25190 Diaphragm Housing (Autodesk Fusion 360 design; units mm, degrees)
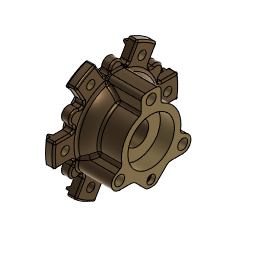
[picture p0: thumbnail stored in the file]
parameter "Bell_Tolerance" = 0.0992 (= "( 1 / 256 ) * 1 in")
parameter "Alignment_Boss_Tolerance" = 0.1984 (= "( 1 / 128 ) * 1 in")
parameter "Dowel_Hole_Tolerance" = 0.0992 (= "( 1 / 256 ) * 1 in")
parameter "Dowl_And_Bell_Depth_Tolerance" = 0.7937 (= "( 1 / 32 ) * 1 in")
sketch "Main Profile" plane through (0, 0, 0) normal (0, 1, 0) x axis (1, 0, 0)
  line L1 (0, 25.4) -> (0, -25.4)
  line L2 (0, -26.9875) -> (0, -25.4)
  line L3 (1.3048, -26.9875) -> (0, -26.9875)
  line L4 (3.7879, -13.6274) -> (1.5528, -24.1426)
  line L5 (31.75, -11.1125) -> (6.8935, -11.1125)
  line L6 (65.0875, 0) -> (0, 0)
  line L7 (6.2281, -21.4795) -> (4.0817, -25.3518)
  line L8 (4.3224, -11.1125) -> (6.8935, -11.1125)
  line L9 (3.7879, -13.6274) -> (4.3224, -11.1125)
  line L10 (19.05, -19.8438) -> (9.0051, -19.8438)
  line L11 (1.3048, -26.9875) -> (3.175, -26.9875)
  line L12 (7.1348, -19.8438) -> (9.0051, -19.8438)
  line L13 (6.2281, -21.4795) -> (7.1348, -19.8438)
  line L14 (3.175, -26.9875) -> (4.0817, -25.3518)
  line L15 (31.75, -22.225) -> (31.75, -11.1125)
  line L16 (44.45, -22.225) -> (31.75, -22.225)
  line L17 (65.0875, 0) -> (65.0875, -34.925)
  line L18 (44.45, -44.45) -> (44.45, -22.225)
  line L19 (3.175, -44.45) -> (44.45, -44.45)
  line L20 (3.175, -41.275) -> (3.175, -44.45)
  line L21 (0, -41.275) -> (3.175, -41.275)
  line L22 (0, -38.1) -> (0, -41.275)
  line L23 (0, -38.1) -> (0, -26.9875)
  line L24 (22.225, -11.1125) -> (22.225, -44.45)
  line L25 (96.52, -34.925) -> (22.225, -34.925)
  line L26 (20.6375, -39.6875) -> (44.45, -39.6875)
  line L27 (20.6375, -30.1625) -> (20.6375, -39.6875)
  line L28 (44.45, -30.1625) -> (20.6375, -30.1625)
  line L29 (25.4, -30.1625) -> (20.6375, -34.925)
  line L30 (25.4, -39.6875) -> (20.6375, -34.925)
  line L31 (44.45, -42.8625) -> (3.175, -42.8625)
  arc A1 centre (0, -23.8125) radius 1.5875 clockwise from (1.5528, -24.1426) to (0, -25.4)
  arc A2 centre (1.3048, -23.8125) radius 3.175 clockwise from (4.0817, -25.3518) to (1.3048, -26.9875)
  arc A3 centre (6.8935, -14.2875) radius 3.175 clockwise from (3.7879, -13.6274) to (6.8935, -11.1125)
  arc A4 centre (9.0051, -23.0187) radius 3.175 clockwise from (6.2281, -21.4795) to (9.0051, -19.8438)
  arc A5 centre (19.05, -23.0187) radius 3.175 clockwise from (19.05, -19.8438) to (21.8627, -24.4917)
  arc A6 centre (-0.6386, -12.708) radius 25.4 clockwise from (21.8627, -24.4917) to (0, -38.1)
  point P4 (0, 0)
  point P1 (0, 0)
  point P6 (0, -23.8125)
  point P15 (0, 0)
  point P24 (6.2281, -21.4795)
  point P22 (3.175, -26.9875)
  point P25 (3.175, -26.9875)
  point P16 (65.0875, 0)
  point P29 (65.0875, 0)
  point P39 (22.225, -11.1125)
  point P38 (22.225, -44.45)
  point P40 (22.225, -34.925)
  point P42 (44.45, -34.925)
  point P28 (65.0875, -34.925)
  point P43 (44.45, -39.6875)
  point P46 (44.45, -30.1625)
  point P47 (20.6375, -34.925)
  point P48 (25.4, -30.1625)
  point P49 (25.4, -39.6875)
  point P50 (3.175, -42.8625)
  point P51 (44.45, -42.8625)
  point P2 (0, -25.4)
  point P3 (0, 25.4)
  point P7 (0, -26.9875)
  point P26 (31.75, -22.225)
  point P27 (44.45, -22.225)
  point P33 (0, -41.275)
  point P34 (0, -38.1)
  point P32 (3.175, -41.275)
  point P44 (20.6375, -39.6875)
  point P45 (20.6375, -30.1625)
  vertical L1
  midpoint L1 P4
  coincident P1 P4
  coincident L1 P6
  parallel L1 L2
  perpendicular L2 L3
  tangent L3 A2
  tangent A1 L4
  tangent L4 A3
  tangent A3 L5
  horizontal L5
  coincident P1 P15
  horizontal L6
  tangent A2 L7
  tangent A3 L8
  parallel L4 L9
  tangent L7 A4
  horizontal L10
  tangent A4 L10
  horizontal L11
  tangent A4 L12
  coincident A4 P24
  tangent A4 L13
  parallel L7 L13
  tangent A2 L14
  coincident P22 P25
  perpendicular L5 L15
  perpendicular L15 L16
  vertical L17
  coincident P16 P29
  perpendicular L16 L18
  perpendicular L18 L19
  perpendicular L19 L20
  perpendicular L20 L21
  perpendicular L21 L22
  vertical L23
  tangent L10 A5
  tangent A5 A6
  vertical L24
  tangent A5 L24
  coincident L5 P39
  coincident L19 P38
  coincident L24 P40
  perpendicular L24 L25
  coincident L18 P42
  coincident L25 P42
  coincident P28 L25
  coincident L18 P43
  perpendicular L18 L26
  perpendicular L25 L27
  coincident L18 P46
  perpendicular L18 L28
  symmetric L25 L26 L28
  midpoint L27 P47
  coincident L28 P48
  coincident L26 P49
  perpendicular L29 L30
  symmetric L25 L29 L30
  horizontal L31
  midpoint L20 P50
  coincident L18 P51
  dimension "d4" distance P2 P3 = 50.8
  dimension "d5" distance P2 P7 = 1.5875 (= "( 1 / 16 ) * 1 in")
  dimension "d6" radius A3 = 3.175 (= "( 1 / 8 ) * 1 in")
  dimension "d7" distance L5 L6 = 11.1125
  dimension "d8" radius A2 = 3.175 (= "( 1 / 8 ) * 1 in")
  dimension "d9" radius A1 = 1.5875 (= "( 1 / 16 ) * 1 in")
  dimension "d12" radius A4 = 3.175 (= "( 1 / 8 ) * 1 in")
  dimension "d13" distance L5 L10 = 8.7313 (= "( 11 / 32 ) * 1 in")
  dimension "d14" distance P7 P22 = 3.175 (= "( 1 / 8 ) * 1 in")
  dimension "d15" angle L4 L7 = 17
  dimension "d17" distance L1 L17 = 65.0875 (= "2 9/16")
  dimension "d18" distance L6 L16 = 22.225 (= "( 7 / 8 ) * 1 in")
  dimension "d19" distance P26 P27 = 12.7 (= "( 1 / 2 ) * 1 in")
  dimension "d21" distance L6 L19 = 44.45 (= "1 3/4")
  dimension "d22" distance P33 P34 = 3.175 (= "( 1 / 8 ) * 1 in")
  dimension "d23" distance P32 P33 = 3.175 (= "( 1 / 8 ) * 1 in")
  dimension "d25" radius A5 = 3.175 (= "( 1 / 8 ) * 1 in")
  dimension "d28" distance L6 L25 = 34.925
  dimension "d32" distance P44 P45 = 9.525 (= "( 3 / 8 ) * 1 in")
  dimension "d33" distance L18 L27 = 23.8125 (= "( 15 / 16 ) * 1 in")
  dimension "d63" distance P4 P34 = 38.1 (= "1 1/2")
  dimension "d64" distance L24 L27 = 1.5875 (= "( 1 / 16 ) * 1 in")
  dimension "d73" distance L6 L31 = 42.8625
  dimension "d127" radius A6 = 25.4
  dimension "d133" distance L18 L22 = 44.45
  dimension "d137" angle L1 L4 = 12
  dimension "d16" Text1-Height = 3.175
  dimension "d29" Text2-Height = 3.175
revolve "Revolve1" sketch "Main Profile" AlongAngle 360
sketch "Flange Profile" plane through (44.45, 0, 0) normal (1, 0, 0) x axis (0, 1, 0)
  line L1 (0, 34.925) -> (0, 0)
  line L2 (-30.2459, -17.4625) -> (0, 0)
  line L3 (30.2459, -17.4625) -> (0, 0)
  line L4 (0, 44.45) -> (0, 34.925)
  line L5 (3.175, 44.45) -> (-3.175, 44.45)
  line L6 (9.525, 29.0994) -> (9.525, 38.1)
  line L7 (34.2147, -10.5884) -> (29.7259, -7.9968)
  line L8 (30.2459, -25.4) -> (16.6688, -25.4)
  line L9 (0, -31.75) -> (0, 0)
  line L10 (0, -38.1) -> (0, -31.75)
  line L11 (3.9688, -38.1) -> (-3.9688, -38.1)
  line L12 (16.6688, -25.4) -> (3.9688, -38.1)
  line L13 (-9.525, 29.0994) -> (-9.525, 38.1)
  line L14 (-34.2147, -10.5884) -> (-29.7259, -7.9968)
  line L15 (-30.2459, -25.4) -> (-16.6688, -25.4)
  line L16 (-16.6688, -25.4) -> (-3.9688, -38.1)
  line L17 (9.525, 26.9408) -> (9.525, 29.0994)
  line L18 (-9.525, 26.9408) -> (-9.525, 29.0994)
  circle C1 centre (0, 0) radius 22.225
  circle C2 centre (0, 34.925) radius 4.7625
  circle C3 centre (-30.2459, -17.4625) radius 4.7625
  circle C4 centre (30.2459, -17.4625) radius 4.7625
  arc A1 centre (3.175, 38.1) radius 6.35 clockwise from (3.175, 44.45) to (9.525, 38.1)
  arc A2 centre (12.7, 29.0994) radius 3.175 clockwise from (11.43, 26.1894) to (9.525, 29.0994)
  arc A3 centre (0, 0) radius 28.575 clockwise from (11.43, 26.1894) to (28.1821, -4.7225)
  arc A4 centre (31.3134, -5.2472) radius 3.175 clockwise from (29.7259, -7.9968) to (28.1821, -4.7225)
  arc A5 centre (30.2459, -17.4625) radius 7.9375 clockwise from (34.2147, -10.5884) to (30.2459, -25.4)
  circle C5 centre (0, -31.75) radius 3.9688
  arc A6 centre (-3.175, 38.1) radius 6.35 clockwise from (-9.525, 38.1) to (-3.175, 44.45)
  arc A7 centre (-12.7, 29.0994) radius 3.175 clockwise from (-9.525, 29.0994) to (-11.43, 26.1894)
  arc A8 centre (0, 0) radius 28.575 clockwise from (-28.1821, -4.7225) to (-11.43, 26.1894)
  arc A9 centre (-31.3134, -5.2472) radius 3.175 clockwise from (-28.1821, -4.7225) to (-29.7259, -7.9968)
  arc A10 centre (-30.2459, -17.4625) radius 7.9375 clockwise from (-30.2459, -25.4) to (-34.2147, -10.5884)
  circle C6 centre (0, 0) radius 42.8625
  arc A11 centre (0, 0) radius 28.575 clockwise from (-11.43, 26.1894) to (11.43, 26.1894)
  arc A12 centre (5.1027, 38.1) radius 4.4223 clockwise from (5.6897, 42.4832) to (9.525, 38.1)
  arc A13 centre (-5.1027, 38.1) radius 4.4223 clockwise from (-9.525, 38.1) to (-5.6897, 42.4832)
  point P1 (0, 0)
  point P3 (0, 0)
  point P4 (0, 34.925)
  point P5 (0, 34.925)
  point P12 (0, 34.925)
  point P16 (0, 44.45)
  point P13 (0, 44.45)
  point P26 (34.2147, -10.5884)
  point P29 (34.2147, -10.5884)
  point P31 (0, -31.75)
  point P32 (0, -31.75)
  point P33 (0, -31.75)
  point P37 (0, -38.1)
  point P34 (0, -38.1)
  point P15 (3.175, 44.45)
  point P40 (-3.175, 44.45)
  point P17 (9.525, 38.1)
  point P39 (-9.525, 38.1)
  point P19 (9.525, 29.0994)
  point P41 (-9.525, 29.0994)
  point P20 (11.43, 26.1894)
  point P43 (-11.43, 26.1894)
  point P22 (28.1821, -4.7225)
  point P45 (-28.1821, -4.7225)
  point P24 (29.7259, -7.9968)
  point P47 (-29.7259, -7.9968)
  point P48 (-34.2147, -10.5884)
  point P27 (16.6688, -25.4)
  point P52 (-16.6688, -25.4)
  point P28 (30.2459, -25.4)
  point P50 (-30.2459, -25.4)
  point P51 (-34.2147, -10.5884)
  point P36 (3.9688, -38.1)
  point P53 (-3.9688, -38.1)
  point P55 (9.525, 26.9408)
  point P56 (-9.525, 29.0994)
  point P57 (-9.525, 26.9408)
  point P58 (5.6897, 42.4832)
  point P61 (-9.525, 38.1)
  point P62 (-5.6897, 42.4832)
  point P23 (0, 0)
  point P35 (-3.9688, -38.1)
  coincident P1 P3
  vertical L1
  coincident P4 P5
  coincident P5 P12
  parallel L1 L4
  horizontal L5
  midpoint L5 P16
  coincident P13 P16
  tangent L5 A1
  vertical L6
  tangent A1 L6
  tangent L6 A2
  tangent A2 A3
  concentric C1 A3
  tangent A3 A4
  tangent A4 L7
  horizontal L8
  tangent L8 A5
  coincident P26 P29
  tangent L7 A5
  concentric C4 A5
  vertical L9
  coincident P31 P32
  coincident P32 P33
  vertical L10
  horizontal L11
  midpoint L11 P37
  coincident P34 L11
  coincident P34 P37
  symmetric L1 P15 P40
  symmetric L1 P17 P39
  symmetric L1 A1 A6
  symmetric L1 P19 P41
  symmetric L1 P20 P43
  symmetric L1 A2 A7
  symmetric L1 P22 P45
  symmetric L1 A3 A8
  symmetric L1 P24 P47
  symmetric L1 A4 A9
  symmetric L1 P26 P48
  symmetric L1 P27 P52
  symmetric L1 P28 P50
  symmetric L1 P29 P51
  symmetric L1 A5 A10
  symmetric L1 P36 P53
  tangent A8 A11
  coincident A11 P55
  tangent A2 L17
  symmetric L1 P19 P56
  symmetric L1 P55 P57
  coincident C6 P58
  tangent L6 A12
  tangent C6 A12
  symmetric L4 P17 P61
  symmetric L4 P58 P62
  symmetric L4 A12 A13
  tangent A5 C6
  dimension "d35" diameter C2 = 9.525 (= "( 3 / 8 ) * 1 in")
  dimension "d36" distance P3 P4 = 34.925 (= "1 3/8")
  dimension "d39" distance P5 L5 = 9.525 (= "( 3 / 8 ) * 1 in")
  dimension "d40" radius A1 = 6.35 (= "( 1 / 4 ) * 1 in")
  dimension "d41" distance P5 L6 = 9.525 (= "( 3 / 8 ) * 1 in")
  dimension "d42" radius A2 = 3.175 (= "( 1 / 8 ) * 1 in")
  dimension "d43" radius A3 = 28.575
  dimension "d44" radius A4 = 3.175 (= "( 1 / 8 ) * 1 in")
  dimension "d46" angle L7 L8 = 30
  dimension "d47" diameter C5 = 7.9375 (= "( 5 / 16 ) * 1 in")
  dimension "d48" distance P32 L11 = 6.35 (= "( 1 / 4 ) * 1 in")
  dimension "d49" distance P23 P32 = 31.75 (= "1 1/4")
  dimension "d50" angle L8 L12 = 135
  dimension "d51" distance P35 P36 = 7.9375 (= "( 5 / 16 ) * 1 in")
  dimension "d38" C-Pattern1-Angle = 360
extrude "Extrude1" cut sketch "Flange Profile" profile of A1 L6 A2 A3 A4 L7 L8 A5 L11 L12 A6 L13 A7 A8 A9 L14 A10 L15 L16 C6 A12 A13 against normal blind 33.3375
work_plane "WorkPlane1" RotateAngle 45
sketch "Body Profile" plane through (12.125, 0, 0) normal (0, -0.7071, 0.7071) x axis (1, 0, 0)
  line L1 (-1.0125, 35.2263) -> (-1.0125, 16.5498)
  curve K1 (-1.0125, 16.5498) -> (5.082, 15.3648)
  line L2 (7.0707, 16.5884) -> (7.0707, 28.575)
  line L3 (-1.0125, 38.755) -> (-1.0125, 35.2263)
  line L4 (11.0013, 28.575) -> (7.0707, 28.575)
  arc A1 centre (-12.7636, 12.708) radius 25.4 clockwise from (-1.0125, 35.2263) to (7.0707, 28.575)
  arc A2 centre (-12.7636, 12.708) radius 28.575 clockwise from (-1.0125, 38.755) to (11.0013, 28.575)
  point P5 (7.0707, 28.575)
  point P8 (7.0707, 28.575)
  point P3 (-1.0125, 35.2263)
  point P7 (-1.0125, 35.2263)
  coincident P5 P8
  coincident P3 P7
  vertical L3
  perpendicular L2 L4
  concentric A1 A2
  dimension "d55" radius A1 = 25.4
  dimension "d56" distance A1 A2 = 3.175 (= "( 1 / 8 ) * 1 in")
revolve "Revolve2" sketch "Body Profile" AlongAngle 360
sketch "Cap Flange Profile" plane through (3.175, 0, 0) normal (-1, 0, 0) x axis (0, -1, 0)
  line L1 (0, 44.45) -> (0, 0)
  line L2 (0, 50.8) -> (0, 44.45)
  line L3 (-43.9941, 25.4) -> (-38.4948, 22.225)
  line L4 (-38.4948, 22.225) -> (0, 0)
  line L5 (-43.9941, -25.4) -> (-38.4948, -22.225)
  line L6 (-38.4948, -22.225) -> (0, 0)
  line L7 (0, -50.8) -> (0, -44.45)
  line L8 (0, -44.45) -> (0, 0)
  line L9 (43.9941, -25.4) -> (38.4948, -22.225)
  line L10 (38.4948, -22.225) -> (0, 0)
  line L11 (43.9941, 25.4) -> (38.4948, 22.225)
  line L12 (38.4948, 22.225) -> (0, 0)
  line L13 (60.325, 0) -> (0, 0)
  line L14 (60.325, -11.1125) -> (60.325, 11.1125)
  line L15 (41.3969, 11.1125) -> (60.325, 11.1125)
  line L16 (41.3969, -11.1125) -> (60.325, -11.1125)
  line L17 (11.0748, 41.407) -> (20.5388, 57.7992)
  line L18 (39.7862, 46.6867) -> (20.5388, 57.7992)
  line L19 (30.3222, 30.2945) -> (39.7862, 46.6867)
  line L20 (-30.3222, 30.2945) -> (-39.7862, 46.6867)
  line L21 (-20.5388, 57.7992) -> (-39.7862, 46.6867)
  line L22 (-11.0748, 41.407) -> (-20.5388, 57.7992)
  line L23 (-41.3969, -11.1125) -> (-60.325, -11.1125)
  line L24 (-60.325, 11.1125) -> (-60.325, -11.1125)
  line L25 (-41.3969, 11.1125) -> (-60.325, 11.1125)
  line L26 (-11.0748, -41.407) -> (-20.5388, -57.7992)
  line L27 (-39.7862, -46.6867) -> (-20.5388, -57.7992)
  line L28 (-30.3222, -30.2945) -> (-39.7862, -46.6867)
  line L29 (30.3222, -30.2945) -> (39.7862, -46.6867)
  line L30 (20.5388, -57.7992) -> (39.7862, -46.6867)
  line L31 (11.0748, -41.407) -> (20.5388, -57.7992)
  circle C1 centre (0, 0) radius 41.275
  circle C2 centre (0, 44.45) radius 1.5875
  arc A1 centre (0, 44.45) radius 6.35 clockwise from (-6.3376, 44.8469) to (6.3376, 44.8469)
  arc A2 centre (9.5064, 45.0453) radius 3.175 clockwise from (8.8508, 41.9387) to (6.3376, 44.8469)
  arc A3 centre (-9.5064, 45.0453) radius 3.175 clockwise from (-6.3376, 44.8469) to (-8.8508, 41.9387)
  circle C3 centre (0, 44.45) radius 3.5719
  arc A4 centre (-38.4948, 22.225) radius 6.35 clockwise from (-42.0073, 16.9349) to (-35.6697, 27.9119)
  arc A5 centre (-34.2572, 30.7554) radius 3.175 clockwise from (-31.8946, 28.6344) to (-35.6697, 27.9119)
  arc A6 centre (-43.7636, 14.2899) radius 3.175 clockwise from (-42.0073, 16.9349) to (-40.7454, 13.3044)
  circle C4 centre (-38.4948, 22.225) radius 3.5719
  circle C5 centre (-38.4948, 22.225) radius 1.5875
  arc A7 centre (-38.4948, -22.225) radius 6.35 clockwise from (-35.6697, -27.9119) to (-42.0073, -16.9349)
  arc A8 centre (-43.7636, -14.2899) radius 3.175 clockwise from (-40.7454, -13.3044) to (-42.0073, -16.9349)
  arc A9 centre (-34.2572, -30.7554) radius 3.175 clockwise from (-35.6697, -27.9119) to (-31.8946, -28.6344)
  circle C6 centre (-38.4948, -22.225) radius 3.5719
  circle C7 centre (-38.4948, -22.225) radius 1.5875
  arc A10 centre (0, -44.45) radius 6.35 clockwise from (6.3376, -44.8469) to (-6.3376, -44.8469)
  arc A11 centre (-9.5064, -45.0453) radius 3.175 clockwise from (-8.8508, -41.9387) to (-6.3376, -44.8469)
  arc A12 centre (9.5064, -45.0453) radius 3.175 clockwise from (6.3376, -44.8469) to (8.8508, -41.9387)
  circle C8 centre (0, -44.45) radius 3.5719
  circle C9 centre (0, -44.45) radius 1.5875
  arc A13 centre (38.4948, -22.225) radius 6.35 clockwise from (42.0073, -16.9349) to (35.6697, -27.9119)
  arc A14 centre (34.2572, -30.7554) radius 3.175 clockwise from (31.8946, -28.6344) to (35.6697, -27.9119)
  arc A15 centre (43.7636, -14.2899) radius 3.175 clockwise from (42.0073, -16.9349) to (40.7454, -13.3044)
  circle C10 centre (38.4948, -22.225) radius 3.5719
  circle C11 centre (38.4948, -22.225) radius 1.5875
  arc A16 centre (38.4948, 22.225) radius 6.35 clockwise from (35.6697, 27.9119) to (42.0073, 16.9349)
  arc A17 centre (43.7636, 14.2899) radius 3.175 clockwise from (40.7454, 13.3044) to (42.0073, 16.9349)
  arc A18 centre (34.2572, 30.7554) radius 3.175 clockwise from (35.6697, 27.9119) to (31.8946, 28.6344)
  circle C12 centre (38.4948, 22.225) radius 3.5719
  circle C13 centre (38.4948, 22.225) radius 1.5875
  circle C14 centre (0, 0) radius 60.325
  circle C15 centre (0, 0) radius 42.8625
  circle C16 centre (49.2125, 0) radius 3.9688
  circle C17 centre (24.6063, 42.6193) radius 3.9688
  circle C18 centre (-24.6062, 42.6193) radius 3.9688
  circle C19 centre (-49.2125, 0) radius 3.9688
  circle C20 centre (-24.6063, -42.6193) radius 3.9688
  circle C21 centre (24.6062, -42.6193) radius 3.9688
  arc A19 centre (9.5071, 45.0487) radius 3.1785 clockwise from (12.2597, 43.4595) to (8.8508, 41.9387)
  arc A20 centre (-9.5071, 45.0487) radius 3.1785 clockwise from (-8.8508, 41.9387) to (-12.2597, 43.4595)
  arc A21 centre (-43.7669, 14.291) radius 3.1785 clockwise from (-40.7454, 13.3044) to (-43.7669, 11.1125)
  arc A22 centre (-34.2598, 30.7577) radius 3.1785 clockwise from (-31.5071, 32.347) to (-31.8946, 28.6344)
  arc A23 centre (-34.2598, -30.7577) radius 3.1785 clockwise from (-31.8946, -28.6344) to (-31.5071, -32.347)
  arc A24 centre (-43.7669, -14.291) radius 3.1785 clockwise from (-43.7669, -11.1125) to (-40.7454, -13.3044)
  arc A25 centre (9.5071, -45.0487) radius 3.1785 clockwise from (8.8508, -41.9387) to (12.2597, -43.4595)
  arc A26 centre (-9.5071, -45.0487) radius 3.1785 clockwise from (-12.2597, -43.4595) to (-8.8508, -41.9387)
  arc A27 centre (43.7669, -14.291) radius 3.1785 clockwise from (40.7454, -13.3044) to (43.7669, -11.1125)
  arc A28 centre (34.2598, -30.7577) radius 3.1785 clockwise from (31.5071, -32.347) to (31.8946, -28.6344)
  arc A29 centre (34.2598, 30.7577) radius 3.1785 clockwise from (31.8946, 28.6344) to (31.5071, 32.347)
  arc A30 centre (43.7669, 14.291) radius 3.1785 clockwise from (43.7669, 11.1125) to (40.7454, 13.3044)
  circle C22 centre (0, 0) radius 57.15
  circle C23 centre (0, 0) radius 53.975
  point P1 (0, 0)
  point P3 (0, 0)
  point P4 (0, 44.45)
  point P5 (0, 44.45)
  point P6 (0, 44.45)
  point P8 (0, 44.45)
  point P9 (0, 50.8)
  point P84 (60.325, 0)
  point P81 (60.325, 0)
  point P66 (0, 0)
  point P85 (0, 0)
  point P88 (49.2125, 0)
  point P11 (8.8508, 41.9387)
  point P13 (-8.8508, 41.9387)
  point P86 (41.3969, 11.1125)
  point P87 (41.3969, -11.1125)
  point P114 (12.2597, 43.4595)
  point P116 (-12.2597, 43.4595)
  point P27 (0, 0)
  point P148 (0, 0)
  point P149 (0, 0)
  point P150 (42.8625, 0)
  point P79 (0, 0)
  point P82 (60.325, 11.1125)
  point P83 (60.325, -11.1125)
  point P40 (0, 0)
  coincident P1 P3
  vertical L1
  coincident P4 P5
  concentric C2 A1
  coincident P6 P8
  coincident P9 A1
  parallel L1 L2
  tangent A1 A2
  tangent A1 A3
  concentric C2 C3
  horizontal L13
  vertical L14
  midpoint L14 P84
  coincident P81 P84
  coincident P66 P85
  coincident P84 C14
  perpendicular L14 L15
  perpendicular L14 L16
  coincident L13 P88
  coincident P11 C15
  tangent A2 C15
  coincident P13 C15
  tangent A3 C15
  coincident P86 C15
  coincident P87 C15
  coincident L17 P114
  tangent A2 A19
  tangent L17 A19
  coincident L22 P116
  tangent A3 A20
  tangent L22 A20
  coincident P27 P148
  coincident P1 P149
  coincident L13 P150
  coincident C15 P150
  dimension "d58" distance P3 P4 = 44.45 (= "1 3/4")
  dimension "d59" diameter C2 = 3.175 (= "( 1 / 8 ) * 1 in")
  dimension "d60" distance P1 P9 = 50.8
  dimension "d66" radius A2 = 3.175 (= "( 1 / 8 ) * 1 in")
  dimension "d67" radius A3 = 3.175 (= "d66")
  dimension "d68" diameter C3 = 7.1437 (= "( 9 / 32 ) * 1 in")
  dimension "d71" distance P79 P81 = 60.325
  dimension "d72" distance P82 P83 = 22.225 (= "( 7 / 8 ) * 1 in")
  dimension "d76" diameter C16 = 7.9375 (= "( 5 / 16 ) * 1 in")
  dimension "d77" distance P40 P88 = 49.2125 (= "1 15/16")
  dimension "d102" distance C14 C22 = 3.175 (= "( 1 / 8 ) * 1 in")
  dimension "d103" distance C22 C23 = 3.175 (= "( 1 / 8 ) * 1 in")
  dimension "d70" C-Pattern1-Angle = 360
  dimension "d79" C-Pattern2-Angle = 360
  dimension "d83" C-Pattern3-Angle = 360
extrude "Extrude3" add sketch "Cap Flange Profile" profile of C2 A1 A2 A3 A4 A5 A6 C5 A7 A8 A9 C7 A10 A11 A12 C9 A13 A14 A15 C11 A16 A17 A18 C13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 against normal blind 7.9375
fillet "Fillet1" radius 6.35 (= "( 1 / 4 ) * 1 in")
fillet "Fillet2" radius 3.175 (= "( 1 / 8 ) * 1 in")
fillet "Fillet4" radius 1.5875 (= "( 1 / 16 ) * 1 in")
chamfer "Chamfer1" distance 3.175 (= "( 1 / 8 ) * 1 in") distance 0.7937 (= "( 1 / 32 ) * 1 in")
extrude "Extrude7" add sketch "Cap Flange Profile" profile of L15 L16 L17 L19 L20 L22 L23 L25 L26 L28 L29 L31 C22 C23 along normal blind 3.175
chamfer "Chamfer2" distance 1.5875 (= "( 1 / 16 ) * 1 in") distance 3.175
fillet "Fillet5" radius 1.5875 (= "( 1 / 16 ) * 1 in")
extrude "Extrude8" cut sketch "Flange Profile" profile of C2 C3 C4 against normal blind 19.05 (magnitude of "( -3 / 4 ) * 1 in")
extrude "Extrude9" cut sketch "Flange Profile" profile of C5 against normal blind 3.175 (magnitude of "( -1 / 8 ) * 1 in")
offset_faces "OffsetFaces1"
sketch "Input Orifice Profile" plane through (0, 0, 0) normal (0, 1, 0) x axis (1, 0, 0)
  line L1 (41.275, 27.7812) -> (41.275, 35.7188)
  line L2 (44.45, 27.7812) -> (44.45, 35.7188)
  line L3 (21.8627, -24.4917) -> (21.8627, 24.4917)
  line L4 (-2.6231, 38.1) -> (0, 38.1)
  line L5 (0, -41.275) -> (0, 41.275)
  line L6 (20.8357, 26.2733) -> (41.275, 31.75)
  line L7 (20.124, 22.7956) -> (43.6302, 29.0941)
  line L8 (19.3023, 25.8624) -> (20.124, 22.7956)
  line L9 (20.8357, 26.2733) -> (19.3023, 25.8624)
  line L10 (42.8084, 32.1609) -> (41.275, 31.75)
  line L11 (43.6302, 29.0941) -> (42.8084, 32.1609)
  line L12 (21.8627, -24.4917) -> (21.8627, 24.4917)
  line L13 (0, -38.1) -> (0, 38.1)
  line L14 (0, -38.1) -> (0, 38.1)
  arc A1 centre (-0.6386, 12.708) radius 25.4 clockwise from (0, 38.1) to (21.8627, 24.4917)
  point P8 (0, 38.1)
  point P12 (41.275, 31.75)
  point P22 (0, 38.1)
  point P25 (0, 38.1)
  point P18 (21.8627, 24.4917)
  point P24 (21.8627, 24.4917)
  point P13 (20.8357, 26.2733)
  point P10 (0, 41.275)
  point P17 (42.8084, 32.1609)
  point P16 (19.3023, 25.8624)
  horizontal L4
  coincident P8 L5
  midpoint L1 P12
  perpendicular L7 L8
  parallel L6 L10
  parallel L6 L9
  parallel L6 L7
  perpendicular L10 L11
  coincident P22 P25
  coincident P18 P24
  coincident P13 A1
  dimension "d118" distance L4 P10 = 3.175 (= "( 1 / 8 ) * 1 in")
  dimension "d120" angle L1 L6 = 75
  dimension "d121" distance P12 P17 = 1.5875 (= "( 1 / 16 ) * 1 in")
  dimension "d122" distance P13 P16 = 1.5875 (= "( 1 / 16 ) * 1 in")
  dimension "d123" distance L6 L7 = 3.175 (= "( 1 / 8 ) * 1 in")
  dimension "d134" radius A1 = 25.4
revolve "Revolve4" sketch "Input Orifice Profile" AlongAngle 360
fillet "Fillet6" radius 1.5875 (= "( 1 / 16 ) * 1 in")
offset_faces "OffsetFaces3"
chamfer "Chamfer3" distance 0.3969 (= "( 1 / 64 ) * 1 in")
offset_faces "OffsetFaces4"
offset_faces "OffsetFaces5"
named bodies: "25190 Diaphragm Housing"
